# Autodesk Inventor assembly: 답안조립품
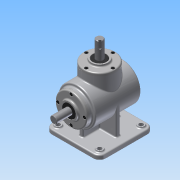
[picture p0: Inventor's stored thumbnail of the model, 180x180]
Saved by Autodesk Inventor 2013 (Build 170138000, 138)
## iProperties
Created: 2015-07
Part Number: 답안조립품
Document SubType Name: Assembly
Designer: Administrator
Author: Administrator
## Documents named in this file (14)
- C:\Users\Administrator\Desktop\450706V1022\답안조립품.iam
- C:\Users\Administrator\Desktop\450706V1022\본체.ipt
- C:\Users\Administrator\Desktop\450706V1022\커버.ipt
- C:\Users\Administrator\Desktop\450706V1022\베어링 6203.ipt
- C:\Users\Administrator\Desktop\450706V1022\오일실.ipt
- C:\Users\Administrator\Desktop\450706V1022\M4.ipt
- C:\Users\Administrator\Desktop\450706V1022\메인 축.ipt
- 메인 축.ipt
- C:\Users\Administrator\Desktop\450706V1022\메인 베벨기어.ipt
- C:\Users\Administrator\Desktop\450706V1022\키 5x5.ipt
- C:\Users\Administrator\Desktop\450706V1022\서브 축.ipt
- 서브 축.ipt
- C:\Users\Administrator\Desktop\450706V1022\서브 베벨기어.ipt
- C:\Users\Administrator\Desktop\450706V1022\키 4x4.ipt
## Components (8 placed, 1 different names)
1. M4:1
2. M4:3
3. M4:4
4. M4:5
5. M4:2
6. M4:6
7. M4:7
8. M4:8
